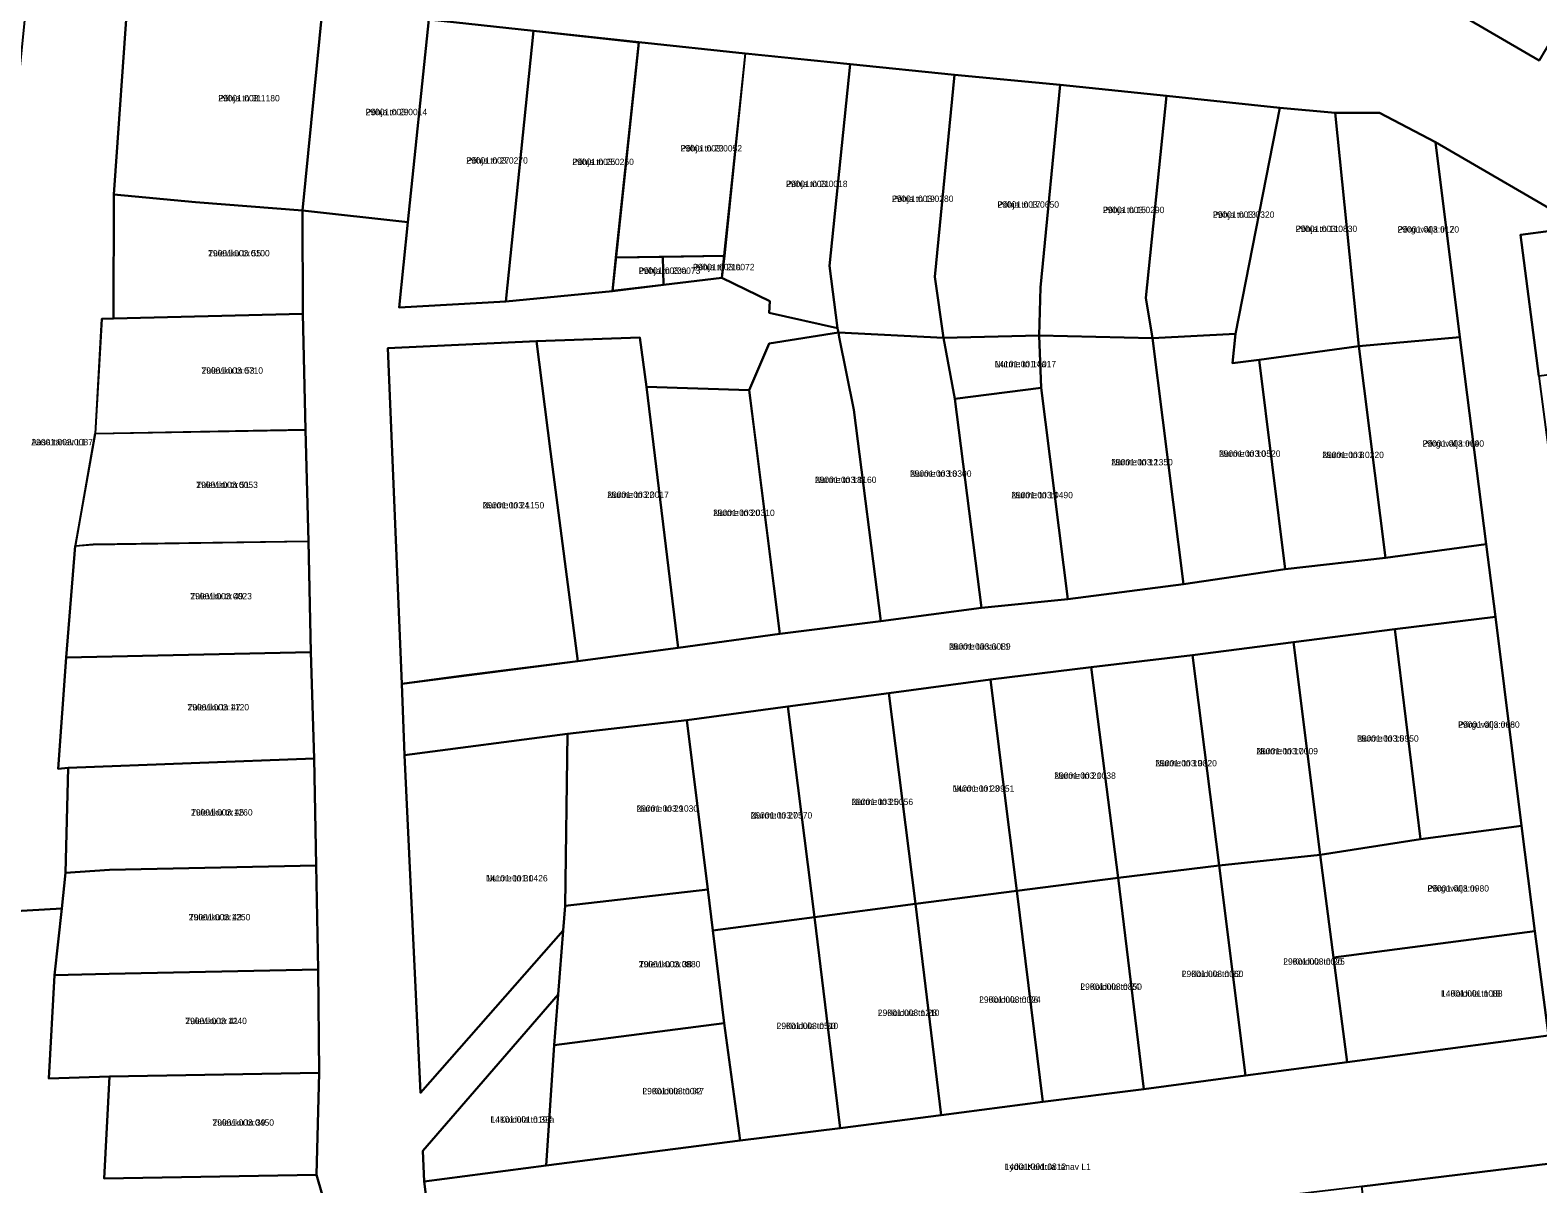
# Model space of a CAD drawing. Extents: x 566437 to 602312, y 6556921 to 6586574.
# Drawn here: x 574798.1 to 575153.3, y 6578480.3 to 6578752.1 of the extents above; entities that cross this region are included whole.
import ezdxf

# ---------------------------------------------------------------- set-up
doc = ezdxf.new("R2010")
doc.units = 0
for name, color, linetype in [('L_AADRESS', 7, 'Continuous'), ('PIIR', 7, 'Continuous'), ('TUNNUS', 7, 'Continuous')]:
    doc.layers.add(name, color=color, linetype=linetype)

msp = doc.modelspace()

# ---------------------------------------------------------------- linework, layer by layer
at = {"layer": 'PIIR'}
for points in [[(574521.37, 6578820.46), (574802.33, 6578791.03), (574822.78, 6578790.98), (574858.87, 6578787.06), (574882.96, 6578784.57), (574906.58, 6578782.12), (574930.36, 6578779.69), (574954.2, 6578776.94), (574978.18, 6578774.66), (575002.44, 6578772.32), (575026.02, 6578769.62), (575048.03, 6578767.52), (575073.8, 6578765.04), (575097.67, 6578762.61), (575119.02, 6578758.61), (575132.89, 6578756.99), (575153.55, 6578744.97)], [(575163.43, 6578705.76), (575129.18, 6578725.71), (575115.93, 6578732.65), (575105.48, 6578732.67), (575092.47, 6578733.85), (575065.82, 6578736.65), (575040.73, 6578739.27), (575015.83, 6578741.61), (574991.26, 6578744.1), (574966.52, 6578746.66), (574941.51, 6578749.29), (574916.65, 6578751.96), (574892.03, 6578754.61), (574866.98, 6578757.27), (574821.21, 6578761.4), (574797.84, 6578763.92)], [(575162.43, 6578461.15), (575159.49, 6578485.53), (575155.77, 6578515.25), (575152.58, 6578539.87), (575149.37, 6578564.68), (575143.27, 6578613.95), (575141.06, 6578631.01), (575134.92, 6578679.77), (575129.18, 6578725.71), (575163.43, 6578705.76), (575149.18, 6578703.91), (575153.51, 6578670.59), (575158.34, 6578633.4), (575160.3, 6578616.24), (575166.52, 6578566.63), (575169.62, 6578541.82), (575173.44, 6578517.14), (575176.67, 6578488.04), (575178.68, 6578470.81)], [(574866.91, 6578477.79), (574865.58, 6578482.46), (574866.21, 6578506.47), (574865.94, 6578530.8), (574865.47, 6578555.33), (574865.02, 6578580.55), (574864.23, 6578605.61), (574863.67, 6578631.64), (574862.95, 6578657.95), (574862.32, 6578685.32), (574862.25, 6578709.62), (574887.09, 6578706.89), (574885.05, 6578686.8), (574910.16, 6578688.23), (574935.31, 6578690.67), (574947.29, 6578692.14), (574961.07, 6578693.8), (574972.32, 6578688.3), (574972.18, 6578685.54), (574988.3, 6578681.92), (574988.5, 6578680.86), (574972.2, 6578678.28), (574967.48, 6578667.34), (574943.28, 6578668.1), (574941.72, 6578679.69), (574917.38, 6578678.88), (574882.34, 6578677.23), (574885.64, 6578598.15), (574886.34, 6578581.33), (574890.11, 6578501.78), (574923.71, 6578539.98), (574922.51, 6578524.93), (574914.99, 6578516.22), (574890.59, 6578488.14), (574890.93, 6578480.92), (574894.59, 6578451.98)], [(574775.61, 6578543.46), (574805.57, 6578545.21), (574803.89, 6578529.49), (574802.54, 6578505.13), (574816.84, 6578505.62), (574815.59, 6578481.57), (574865.58, 6578482.46), (574866.91, 6578477.79)]]:
    msp.add_lwpolyline(points, dxfattribs=at)
for points in [[(575132.89, 6578756.99), (575158.14, 6578800.23), (575178.98, 6578787.96), (575156.52, 6578749.99), (575153.55, 6578744.97)], [(574797.84, 6578763.92), (574821.21, 6578761.4), (574817.87, 6578713.42), (574817.76, 6578684.21), (574815.04, 6578684.1), (574813.47, 6578657.09), (574808.76, 6578630.6), (574806.63, 6578604.36), (574804.71, 6578578.11), (574807.07, 6578578.37), (574806.47, 6578553.64), (574805.57, 6578545.21), (574775.61, 6578543.46), (574777.76, 6578566.28), (574780.61, 6578596.15), (574783.62, 6578626.03), (574787.49, 6578655.77), (574790.41, 6578686.15), (574793.02, 6578716.04)], [(574866.98, 6578757.27), (574862.25, 6578709.62), (574837.07, 6578711.62), (574817.87, 6578713.42), (574821.21, 6578761.4)], [(574892.03, 6578754.61), (574887.09, 6578706.89), (574862.25, 6578709.62), (574866.98, 6578757.27)], [(574916.65, 6578751.96), (574910.16, 6578688.23), (574885.05, 6578686.8), (574887.09, 6578706.89), (574892.03, 6578754.61)], [(574916.65, 6578751.96), (574941.51, 6578749.24), (574935.31, 6578690.67), (574910.16, 6578688.23)], [(574941.51, 6578749.29), (574966.52, 6578746.66), (574961.66, 6578698.99), (574936.1, 6578698.58)], [(574991.26, 6578744.1), (574986.37, 6578696.61), (574988.3, 6578681.92), (574972.18, 6578685.54), (574972.32, 6578688.3), (574961.07, 6578693.8), (574961.59, 6578699.02), (574966.6, 6578746.64)], [(574988.3, 6578681.92), (574986.37, 6578696.61), (574991.26, 6578744.1), (575015.83, 6578741.61), (575011.19, 6578694), (575013.24, 6578679.6), (574988.5, 6578680.86)], [(575040.73, 6578739.27), (575036.07, 6578691.51), (575035.76, 6578680.16), (575013.24, 6578679.6), (575011.19, 6578694), (575015.83, 6578741.61)], [(575036.07, 6578691.51), (575040.73, 6578739.27), (575065.82, 6578736.65), (575060.92, 6578689.07), (575062.52, 6578679.55), (575035.76, 6578680.16)], [(575060.92, 6578689.07), (575065.82, 6578736.65), (575092.47, 6578733.85), (575082.03, 6578680.59), (575062.52, 6578679.55)], [(575105.48, 6578732.67), (575111.11, 6578677.65), (575087.58, 6578674.47), (575081.3, 6578673.66), (575082.03, 6578680.59), (575092.47, 6578733.85)], [(575105.48, 6578732.67), (575115.93, 6578732.65), (575129.18, 6578725.71), (575134.92, 6578679.77), (575111.11, 6578677.65)], [(574817.87, 6578713.42), (574837.07, 6578711.62), (574862.25, 6578709.62), (574862.32, 6578685.32), (574817.76, 6578684.21)], [(575153.51, 6578670.59), (575149.18, 6578703.91), (575163.43, 6578705.76), (575210.11, 6578677.94), (575185.23, 6578674.71)], [(574936.1, 6578698.58), (574947.19, 6578698.74), (574947.29, 6578692.14), (574935.32, 6578690.68)], [(574947.19, 6578698.74), (574961.66, 6578698.99), (574961.06, 6578693.81), (574947.29, 6578692.14)], [(574862.98, 6578657.99), (574813.5, 6578657.04), (574815.04, 6578684.1), (574817.76, 6578684.21), (574862.32, 6578685.32)], [(574920.71, 6578652.9), (574927.1, 6578603.49), (574900.31, 6578600.06), (574885.64, 6578598.15), (574882.34, 6578677.23), (574917.38, 6578678.88)], [(574941.72, 6578679.69), (574943.28, 6578668.1), (574950.76, 6578606.64), (574927.1, 6578603.49), (574920.71, 6578652.9), (574917.38, 6578678.88)], [(574968.5, 6578659.36), (574967.48, 6578667.34), (574972.2, 6578678.28), (574988.5, 6578680.86), (574988.69, 6578679.83), (574992.14, 6578662.67), (574998.47, 6578612.87), (574974.71, 6578609.88)], [(575013.24, 6578679.6), (575015.9, 6578665.28), (575022.22, 6578616.04), (574998.47, 6578612.87), (574992.14, 6578662.67), (574988.69, 6578679.83), (574988.5, 6578680.86)], [(575015.9, 6578665.28), (575013.24, 6578679.6), (575035.76, 6578680.16), (575036.27, 6578667.83)], [(575062.52, 6578679.55), (575069.77, 6578621.61), (575042.58, 6578618.1), (575036.27, 6578667.83), (575035.76, 6578680.16)], [(575082.03, 6578680.59), (575081.3, 6578673.66), (575087.58, 6578674.47), (575093.76, 6578625.15), (575069.77, 6578621.61), (575062.52, 6578679.55)], [(575111.11, 6578677.65), (575134.92, 6578679.77), (575141.06, 6578631.01), (575117.4, 6578627.84)], [(575087.58, 6578674.47), (575111.11, 6578677.65), (575117.4, 6578627.84), (575093.76, 6578625.15)], [(574974.71, 6578609.88), (574950.76, 6578606.64), (574943.28, 6578668.1), (574967.48, 6578667.34)], [(575015.9, 6578665.28), (575036.27, 6578667.83), (575042.58, 6578618.1), (575022.22, 6578616.04)], [(574813.47, 6578657.09), (574862.95, 6578657.95), (574863.67, 6578631.64), (574812.96, 6578630.92), (574808.78, 6578630.59)], [(574808.76, 6578630.6), (574812.95, 6578630.93), (574863.66, 6578631.71), (574864.23, 6578605.61), (574810.19, 6578604.38), (574806.63, 6578604.36)], [(574885.64, 6578598.15), (574927.1, 6578603.49), (574950.76, 6578606.64), (574974.71, 6578609.88), (574998.47, 6578612.87), (575022.22, 6578616.04), (575042.58, 6578618.1), (575069.77, 6578621.61), (575093.76, 6578625.15), (575117.4, 6578627.84), (575141.06, 6578631.01), (575143.27, 6578613.95), (575119.57, 6578610.99), (575095.74, 6578607.93), (575071.93, 6578604.9), (575048.08, 6578602.07), (575024.32, 6578599.13), (575000.35, 6578595.94), (574976.56, 6578592.8), (574952.83, 6578589.6), (574924.7, 6578586.36), (574886.34, 6578581.33)], [(575095.74, 6578607.93), (575119.57, 6578610.99), (575125.62, 6578561.5), (575101.99, 6578557.82)], [(575149.37, 6578564.68), (575125.62, 6578561.5), (575119.57, 6578610.99), (575143.27, 6578613.95)], [(575095.74, 6578607.93), (575101.99, 6578557.82), (575078.23, 6578555.3), (575071.93, 6578604.9)], [(574804.71, 6578578.11), (574806.63, 6578604.36), (574810.19, 6578604.38), (574864.23, 6578605.61), (574865.02, 6578580.55), (574807.07, 6578578.37)], [(575048.08, 6578602.07), (575071.93, 6578604.9), (575078.23, 6578555.3), (575054.38, 6578552.45)], [(575048.08, 6578602.07), (575054.38, 6578552.45), (575030.53, 6578549.38), (575027.19, 6578576.18), (575026.3, 6578583.27), (575024.32, 6578599.13)], [(575027.19, 6578576.18), (575030.53, 6578549.38), (575006.64, 6578546.33), (575000.35, 6578595.94), (575024.32, 6578599.13), (575026.3, 6578583.27)], [(574976.56, 6578592.8), (574982.85, 6578543.19), (574958.94, 6578539.98), (574957.75, 6578549.67), (574952.83, 6578589.6)], [(574976.56, 6578592.8), (575000.35, 6578595.94), (575006.64, 6578546.33), (574982.85, 6578543.19)], [(574957.75, 6578549.67), (574924.17, 6578545.82), (574924.7, 6578586.36), (574952.83, 6578589.6)], [(574923.71, 6578539.98), (574890.11, 6578501.78), (574886.34, 6578581.33), (574924.7, 6578586.36), (574924.17, 6578545.82)], [(574806.47, 6578553.64), (574807.07, 6578578.37), (574865.02, 6578580.55), (574865.47, 6578555.33), (574816.84, 6578554.29)], [(575101.99, 6578557.82), (575125.62, 6578561.5), (575149.37, 6578564.68), (575152.58, 6578539.87), (575105.1, 6578533.69)], [(575101.99, 6578557.82), (575105.1, 6578533.69), (575108.34, 6578508.99), (575084.4, 6578505.83), (575078.23, 6578555.3)], [(574865.94, 6578530.8), (574816.73, 6578529.81), (574803.89, 6578529.49), (574805.57, 6578545.21), (574806.47, 6578553.64), (574816.84, 6578554.29), (574865.47, 6578555.33)], [(575084.4, 6578505.83), (575060.46, 6578502.64), (575054.38, 6578552.45), (575078.23, 6578555.3)], [(575060.46, 6578502.64), (575036.69, 6578499.65), (575030.53, 6578549.38), (575054.38, 6578552.45)], [(574924.17, 6578545.82), (574957.75, 6578549.67), (574958.94, 6578539.98), (574961.63, 6578518.22), (574921.58, 6578512.98), (574922.51, 6578524.93), (574923.71, 6578539.98)], [(575036.69, 6578499.65), (575012.75, 6578496.55), (575006.64, 6578546.33), (575030.53, 6578549.38)], [(574958.94, 6578539.98), (574982.85, 6578543.19), (574988.95, 6578493.46), (574965.35, 6578490.51), (574961.63, 6578518.22)], [(575006.64, 6578546.33), (575012.75, 6578496.55), (574988.95, 6578493.46), (574982.85, 6578543.19)], [(575155.77, 6578515.25), (575108.34, 6578508.99), (575105.1, 6578533.69), (575152.58, 6578539.87)], [(574803.89, 6578529.49), (574816.73, 6578529.81), (574865.94, 6578530.8), (574866.21, 6578506.47), (574816.84, 6578505.62), (574802.54, 6578505.13)], [(574890.93, 6578480.92), (574890.59, 6578488.14), (574914.99, 6578516.22), (574922.51, 6578524.93), (574921.58, 6578512.98), (574919.67, 6578484.66)], [(574894.59, 6578451.98), (574890.93, 6578480.92), (574919.67, 6578484.66), (574965.35, 6578490.51), (574988.95, 6578493.46), (575012.75, 6578496.55), (575036.69, 6578499.65), (575060.46, 6578502.64), (575084.4, 6578505.83), (575108.34, 6578508.99), (575155.77, 6578515.25), (575159.49, 6578485.53), (575111.77, 6578479.74), (575087.94, 6578476.85), (575064.25, 6578474.01), (575040.31, 6578471.11), (575016.67, 6578468.11), (574992.48, 6578465.05), (574968.66, 6578461.7), (574917.39, 6578455.46)], [(574921.58, 6578512.98), (574961.63, 6578518.22), (574965.35, 6578490.51), (574919.67, 6578484.66)], [(574866.21, 6578506.47), (574865.58, 6578482.46), (574815.59, 6578481.57), (574816.84, 6578505.62)], [(575162.43, 6578461.15), (575114.95, 6578455.2), (575111.77, 6578479.74), (575159.49, 6578485.53)]]:
    msp.add_lwpolyline(points, close=True, dxfattribs=at)

# ---------------------------------------------------------------- texts
at = {"layer": 'L_AADRESS'}
for s, p in [('Põhja tn 31', (574842.42, 6578735.34)), ('Põhja tn 29', (574877.14, 6578732.09)), ('Põhja tn 23', (574951.31, 6578723.54)), ('Põhja tn 27', (574900.85, 6578720.68)), ('Põhja tn 25', (574925.83, 6578720.35)), ('Põhja tn 21', (574976.16, 6578715.15)), ('Põhja tn 19', (575001.1, 6578711.66)), ('Põhja tn 17', (575025.96, 6578710.29)), ('Põhja tn 15', (575050.79, 6578709.02)), ('Põhja tn 13', (575076.7, 6578707.91)), ('Põhja tn 11', (575096.2, 6578704.57)), ('Põrguvälja tn 2', (575120.2, 6578704.44)), ('Tuleviku tn 55', (574840.05, 6578698.82)), ('Põhja tn 23a', (574941.48, 6578694.71)), ('Põhja tn 21a', (574954.25, 6578695.57)), ('Tuleviku tn 53', (574838.48, 6578671.18)), ('Nurme tn 14a', (575025.29, 6578672.72)), ('Aasa tänav L1', (574798.41, 6578654.33)), ('Põrguvälja tn 4', (575126.09, 6578653.99)), ('Nurme tn 12', (575052.77, 6578649.59)), ('Nurme tn 10', (575078.14, 6578651.61)), ('Nurme tn 8', (575102.49, 6578651.31)), ('Nurme tn 18', (574982.97, 6578645.45)), ('Nurme tn 16', (575005.36, 6578646.9)), ('Tuleviku tn 51', (574837.26, 6578644.27)), ('Nurme tn 22', (574934.07, 6578641.93)), ('Nurme tn 14', (575029.24, 6578641.85)), ('Nurme tn 24', (574904.72, 6578639.45)), ('Nurme tn 20', (574959, 6578637.68)), ('Tuleviku tn 49', (574835.85, 6578618.04)), ('Nurme tänav L1', (575014.57, 6578606.17)), ('Tuleviku tn 47', (574835.19, 6578591.86)), ('Põrguvälja tn 6', (575134.47, 6578587.77)), ('Nurme tn 15', (575110.68, 6578584.51)), ('Nurme tn 17', (575086.96, 6578581.52)), ('Nurme tn 19', (575063.15, 6578578.68)), ('Nurme tn 21', (575039.35, 6578575.75)), ('Nurme tn 23', (575015.44, 6578572.7)), ('Tuleviku tn 45', (574836.03, 6578567.1)), ('Nurme tn 29', (574940.96, 6578567.99)), ('Nurme tn 25', (574991.6, 6578569.57)), ('Nurme tn 27', (574967.84, 6578566.4)), ('Nurme tn 31', (574905.52, 6578551.57)), ('Põrguvälja tn 8', (575127.24, 6578549.19)), ('Tuleviku tn 43', (574835.49, 6578542.41)), ('Tuleviku tn 38', (574941.51, 6578531.33)), ('L. Koidula tn 20', (575093.29, 6578531.95)), ('L. Koidula tn 22', (575069.39, 6578529.04)), ('L. Koidula tn 24', (575045.5, 6578526.03)), ('L. Koidula tn 18', (575130.45, 6578524.43)), ('L. Koidula tn 26', (575021.66, 6578522.98)), ('Tuleviku tn 41', (574834.67, 6578517.96)), ('L. Koidula tn 30', (574973.95, 6578516.79)), ('L. Koidula tn 28', (574997.8, 6578519.89)), ('L. Koidula tn 32', (574942.34, 6578501.44)), ('Tuleviku tn 39', (574841.06, 6578494.02)), ('L. Koidula tn 32a', (574906.55, 6578494.73)), ('Lydia Koidula tänav L1', (575027.67, 6578483.62))]:
    msp.add_text(s, height=1.5, dxfattribs=at).set_placement(p)
at = {"layer": 'TUNNUS'}
for s, p in [('29001:003:1180', (574842.42, 6578735.34)), ('29001:003:0014', (574877.14, 6578732.09)), ('29001:003:0052', (574951.31, 6578723.54)), ('29001:003:0270', (574900.85, 6578720.68)), ('29001:003:0250', (574925.83, 6578720.35)), ('29001:003:0018', (574976.16, 6578715.15)), ('29001:003:0280', (575001.1, 6578711.66)), ('29001:003:0650', (575025.96, 6578710.29)), ('29001:003:0290', (575050.79, 6578709.02)), ('29001:003:0320', (575076.7, 6578707.91)), ('29001:003:0830', (575096.2, 6578704.57)), ('29001:003:0170', (575120.2, 6578704.44)), ('29001:003:0100', (574840.05, 6578698.82)), ('29001:003:0073', (574941.48, 6578694.71)), ('29001:003:0072', (574954.25, 6578695.57)), ('29001:003:0710', (574838.48, 6578671.18)), ('14101:001:0017', (575025.29, 6578672.72)), ('29001:003:0087', (574798.41, 6578654.33)), ('29001:003:0090', (575126.09, 6578653.99)), ('29001:003:1350', (575052.77, 6578649.59)), ('29001:003:0520', (575078.14, 6578651.61)), ('29001:003:0220', (575102.49, 6578651.31)), ('29001:003:1160', (574982.97, 6578645.45)), ('29001:003:0300', (575005.36, 6578646.9)), ('29001:003:0053', (574837.26, 6578644.27)), ('29001:003:0017', (574934.07, 6578641.93)), ('29001:003:0490', (575029.24, 6578641.85)), ('29001:003:1150', (574904.72, 6578639.45)), ('29001:003:0310', (574959, 6578637.68)), ('29001:003:0023', (574835.85, 6578618.04)), ('29001:003:0089', (575014.57, 6578606.17)), ('29001:003:1120', (574835.19, 6578591.86)), ('29001:003:0680', (575134.47, 6578587.77)), ('29001:003:0950', (575110.68, 6578584.51)), ('29001:003:0009', (575086.96, 6578581.52)), ('29001:003:0820', (575063.15, 6578578.68)), ('29001:003:0038', (575039.35, 6578575.75)), ('14001:001:0951', (575015.44, 6578572.7)), ('29001:003:1260', (574836.03, 6578567.1)), ('29001:003:1030', (574940.96, 6578567.99)), ('29001:003:0056', (574991.6, 6578569.57)), ('29001:003:0570', (574967.84, 6578566.4)), ('14101:001:0426', (574905.52, 6578551.57)), ('29001:003:0980', (575127.24, 6578549.19)), ('29001:003:1250', (574835.49, 6578542.41)), ('29001:003:0880', (574941.51, 6578531.33)), ('29001:003:0025', (575093.29, 6578531.95)), ('29001:003:0060', (575069.39, 6578529.04)), ('29001:003:0850', (575045.5, 6578526.03)), ('14001:001:1088', (575130.45, 6578524.43)), ('29001:003:0024', (575021.66, 6578522.98)), ('29001:003:1240', (574834.67, 6578517.96)), ('29001:003:0510', (574973.95, 6578516.79)), ('29001:003:1210', (574997.8, 6578519.89)), ('29001:003:0047', (574942.34, 6578501.44)), ('29001:003:0450', (574841.06, 6578494.02)), ('14101:001:0197', (574906.55, 6578494.73)), ('14001:001:0812', (575027.67, 6578483.62))]:
    msp.add_text(s, height=1.5, dxfattribs=at).set_placement(p)

doc.saveas('drawing.dxf')
